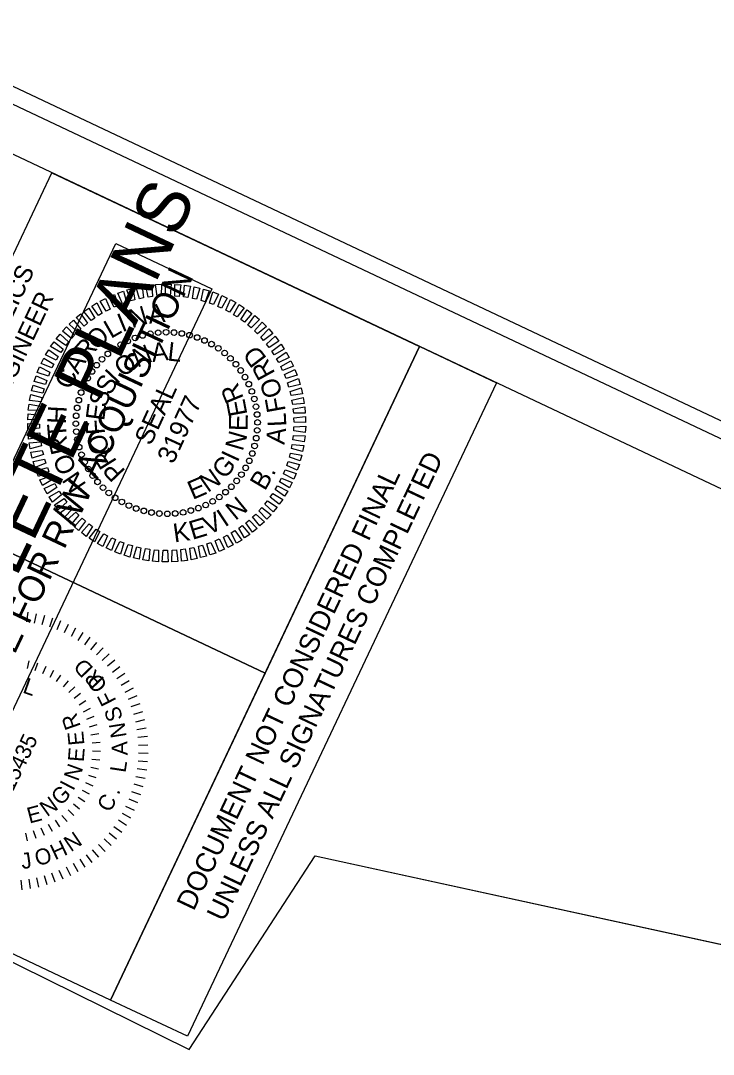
# Model space of a CAD drawing. Extents: x 555566 to 557881, y 503985 to 506091.
# Drawn here: x 556927.2 to 557118.8, y 505805.2 to 506091.2 of the extents above; entities that cross this region are included whole.
import ezdxf

# ---------------------------------------------------------------- set-up
doc = ezdxf.new("R2010")
doc.units = 0
for name, color, linetype in [('Matchline', 7, 'Continuous'), ('Old_Level_21', 7, 'Continuous'), ('Sheet Border Standard 30in CELL', 7, 'Continuous'), ('Sheet Clip Boundary CELL', 7, 'Continuous'), ('Sheet Plot Border Inside CELL', 7, 'Continuous'), ('Sheet Plot Border Outside CELL', 7, 'Continuous'), ('Sheet Sticker Exception Certification CELL', 7, 'Continuous'), ('Sheet Sticker Incomplete CELL', 7, 'Continuous')]:
    doc.layers.add(name, color=color, linetype=linetype)

msp = doc.modelspace()

# ---------------------------------------------------------------- linework, layer by layer
at = {"layer": 'Matchline'}
msp.add_line((557008.7, 505860.07), (557512.37, 505750.31), dxfattribs=at)
at = {"layer": 'Old_Level_21'}
for p, q in [((556929.21, 505927.52), (556928.84, 505924.91)), ((556931.52, 505927.12), (556930.99, 505924.54)), ((556933.79, 505926.59), (556933.11, 505924.04)), ((556936.03, 505925.91), (556935.19, 505923.41)), ((556938.22, 505925.11), (556937.23, 505922.66)), ((556940.36, 505924.17), (556939.23, 505921.79)), ((556942.44, 505923.1), (556941.17, 505920.8)), ((556944.45, 505921.92), (556943.05, 505919.69)), ((556946.39, 505920.61), (556944.85, 505918.47)), ((556948.24, 505919.19), (556946.58, 505917.14)), ((556950.01, 505917.66), (556948.22, 505915.71)), ((556929.48, 505914.07), (556928.99, 505911.93)), ((556951.68, 505916.02), (556949.77, 505914.19)), ((556953.24, 505914.29), (556951.24, 505912.58)), ((556931.85, 505913.4), (556931.16, 505911.32)), ((556934.15, 505912.51), (556933.26, 505910.51)), ((556936.35, 505911.4), (556935.27, 505909.49)), ((556954.7, 505912.46), (556952.6, 505910.88)), ((556937.1, 505908.33), (556938.36, 505910.13)), ((556940.38, 505908.58), (556938.95, 505906.91)), ((556956.05, 505910.55), (556953.85, 505909.1)), ((556957.28, 505908.57), (556955, 505907.25)), ((556942.17, 505906.88), (556940.58, 505905.36)), ((556958.38, 505906.51), (556956.03, 505905.33)), ((556943.78, 505905.03), (556942.06, 505903.67)), ((556945.22, 505903.03), (556943.37, 505901.83)), ((556959.37, 505904.39), (556956.94, 505903.35)), ((556960.22, 505902.21), (556957.73, 505901.33)), ((556946.45, 505900.89), (556944.5, 505899.88)), ((556960.94, 505899.99), (556958.4, 505899.25)), ((556947.47, 505898.65), (556945.43, 505897.83)), ((556961.52, 505897.72), (556958.95, 505897.14)), ((556948.27, 505896.32), (556946.16, 505895.71)), ((556948.84, 505893.92), (556946.68, 505893.52)), ((556961.96, 505895.43), (556959.36, 505895.01)), ((556949.18, 505891.48), (556946.99, 505891.29)), ((556962.27, 505893.12), (556959.65, 505892.85)), ((556962.43, 505890.78), (556959.8, 505890.68)), ((556949.27, 505889.02), (556947.08, 505889.04)), ((556962.45, 505888.45), (556959.82, 505888.5)), ((556949.14, 505886.56), (556946.95, 505886.79)), ((556962.34, 505886.11), (556959.71, 505886.32)), ((556948.15, 505881.74), (556946.05, 505882.38)), ((556948.76, 505884.12), (556946.61, 505884.56)), ((556962.08, 505883.79), (556959.47, 505884.16)), ((556947.32, 505879.42), (556945.29, 505880.27)), ((556961.15, 505879.21), (556958.6, 505879.9)), ((556961.68, 505881.49), (556959.1, 505882.02)), ((556946.26, 505877.19), (556944.32, 505878.23)), ((556960.47, 505876.98), (556957.98, 505877.81)), ((556941.82, 505874.48), (556943.52, 505873.08)), ((556945, 505875.08), (556943.17, 505876.3)), ((556958.73, 505872.64), (556956.35, 505873.77)), ((556959.67, 505874.78), (556957.22, 505875.77)), ((556940.07, 505869.61), (556938.66, 505871.3)), ((556941.89, 505871.27), (556940.32, 505872.82)), ((556957.67, 505870.56), (556955.36, 505871.83)), ((556935.99, 505866.84), (556934.94, 505868.77)), ((556938.1, 505868.12), (556936.86, 505869.94)), ((556955.17, 505866.61), (556953.03, 505868.15)), ((556956.48, 505868.55), (556954.25, 505869.96)), ((556929.09, 505864.28), (556928.63, 505866.43)), ((556931.47, 505864.91), (556930.81, 505867)), ((556933.78, 505865.76), (556932.92, 505867.79)), ((556953.75, 505864.76), (556951.71, 505866.42)), ((556950.58, 505861.33), (556948.76, 505863.23)), ((556952.22, 505862.99), (556950.28, 505864.78)), ((556947.03, 505858.3), (556945.44, 505860.41)), ((556948.85, 505859.76), (556947.14, 505861.77)), ((556941.07, 505854.62), (556939.89, 505856.97)), ((556943.13, 505855.72), (556941.81, 505858)), ((556945.11, 505856.95), (556943.66, 505859.15)), ((556929.99, 505851.04), (556929.57, 505853.64)), ((556932.28, 505851.48), (556931.71, 505854.06)), ((556934.55, 505852.07), (556933.81, 505854.6)), ((556936.77, 505852.79), (556935.89, 505855.27)), ((556938.95, 505853.63), (556937.92, 505856.06)), ((556927.68, 505850.73), (556927.41, 505853.36))]:
    msp.add_line(p, q, dxfattribs=at)
for points in [[(556957.7, 506013.68), (556956.61, 506016.72), (556958.23, 506017.14), (556958.84, 506014)], [(556960.08, 506014.29), (556959.2, 506017.4), (556960.85, 506017.7), (556961.24, 506014.53)], [(556962.5, 506014.73), (556961.84, 506017.9), (556963.51, 506018.08), (556963.67, 506014.89)], [(556964.94, 506015), (556964.51, 506018.21), (556966.18, 506018.28), (556966.12, 506015.08)], [(556967.4, 506015.1), (556967.19, 506018.33), (556968.86, 506018.28), (556968.58, 506015.1)], [(556969.86, 506015.03), (556969.87, 506018.27), (556971.54, 506018.1), (556971.04, 506014.95)], [(556972.3, 506014.79), (556972.54, 506018.02), (556974.19, 506017.74), (556973.47, 506014.62)], [(556974.73, 506014.38), (556975.19, 506017.58), (556976.82, 506017.19), (556975.88, 506014.13)], [(556977.12, 506013.8), (556977.8, 506016.96), (556979.4, 506016.45), (556978.25, 506013.47)], [(556950.89, 506010.88), (556949.19, 506013.63), (556950.69, 506014.37), (556951.94, 506011.43)], [(556953.09, 506011.97), (556951.59, 506014.83), (556953.14, 506015.47), (556954.18, 506012.45)], [(556955.37, 506012.9), (556954.07, 506015.86), (556955.65, 506016.39), (556956.48, 506013.3)], [(556979.46, 506013.06), (556980.36, 506016.16), (556981.92, 506015.54), (556980.57, 506012.65)], [(556981.74, 506012.15), (556982.86, 506015.18), (556984.37, 506014.46), (556982.82, 506011.66)], [(556983.96, 506011.08), (556985.29, 506014.03), (556986.74, 506013.21), (556985, 506010.53)], [(556946.74, 506008.25), (556944.67, 506010.73), (556946.06, 506011.68), (556947.7, 506008.94)], [(556948.77, 506009.64), (556946.88, 506012.26), (556948.33, 506013.11), (556949.78, 506010.26)], [(556986.1, 506009.87), (556987.63, 506012.72), (556989.02, 506011.79), (556987.1, 506009.24)], [(556988.14, 506008.51), (556989.87, 506011.24), (556991.19, 506010.22), (556989.1, 506007.81)], [(556943, 506005.07), (556940.6, 506007.24), (556941.84, 506008.37), (556943.85, 506005.88)], [(556944.81, 506006.72), (556942.58, 506009.06), (556943.89, 506010.1), (556945.72, 506007.48)], [(556990.09, 506007.01), (556992, 506009.61), (556993.25, 506008.5), (556990.99, 506006.24)], [(556941.3, 506003.29), (556938.76, 506005.29), (556939.92, 506006.5), (556942.1, 506004.16)], [(556991.93, 506005.37), (556994.01, 506007.84), (556995.19, 506006.64), (556992.77, 506004.55)], [(556993.64, 506003.62), (556995.9, 506005.93), (556996.99, 506004.66), (556994.43, 506002.73)], [(556938.3, 505999.4), (556935.51, 506001.03), (556936.48, 506002.39), (556938.97, 506000.37)], [(556939.73, 506001.39), (556937.06, 506003.21), (556938.13, 506004.5), (556940.46, 506002.32)], [(556995.24, 506001.74), (556997.65, 506003.9), (556998.64, 506002.55), (556995.96, 506000.81)], [(556937.01, 505997.3), (556934.11, 505998.73), (556934.99, 506000.16), (556937.61, 505998.33)], [(556996.69, 505999.76), (556999.25, 506001.74), (557000.15, 506000.33), (556997.35, 505998.78)], [(556998.01, 505997.69), (557000.7, 505999.48), (557001.49, 505998.01), (556998.6, 505996.66)], [(556935.87, 505995.13), (556932.88, 505996.35), (556933.65, 505997.83), (556936.39, 505996.19)], [(556999.18, 505995.52), (557001.98, 505997.13), (557002.68, 505995.6), (556999.69, 505994.46)], [(556934.88, 505992.87), (556931.81, 505993.89), (556932.48, 505995.42), (556935.33, 505993.97)], [(557000.19, 505993.28), (557003.1, 505994.69), (557003.69, 505993.12), (557000.63, 505992.18)], [(556934.06, 505990.56), (556930.92, 505991.35), (556931.49, 505992.93), (556934.43, 505991.68)], [(557001.05, 505990.98), (557004.05, 505992.18), (557004.52, 505990.57), (557001.41, 505989.85)], [(556933.4, 505988.19), (556930.21, 505988.77), (556930.66, 505990.38), (556933.69, 505989.34)], [(557001.74, 505988.62), (557004.82, 505989.61), (557005.18, 505987.97), (557002.02, 505987.47)], [(556932.57, 505983.35), (556929.34, 505983.47), (556929.56, 505985.13), (556932.7, 505984.52)], [(556932.9, 505985.78), (556929.68, 505986.14), (556930.02, 505987.78), (556933.11, 505986.95)], [(557002.26, 505986.22), (557005.41, 505986.99), (557005.65, 505985.33), (557002.47, 505985.05)], [(556932.42, 505980.89), (556929.18, 505980.8), (556929.29, 505982.47), (556932.46, 505982.08)], [(557002.62, 505983.79), (557005.81, 505984.33), (557005.94, 505982.66), (557002.74, 505982.61)], [(556932.43, 505978.44), (556929.21, 505978.11), (556929.2, 505979.79), (556932.4, 505979.62)], [(557002.81, 505981.34), (557006.03, 505981.66), (557006.04, 505979.99), (557002.85, 505980.15)], [(556932.62, 505975.99), (556929.43, 505975.44), (556929.3, 505977.11), (556932.5, 505977.16)], [(557002.82, 505978.88), (557006.06, 505978.98), (557005.95, 505977.31), (557002.78, 505977.69)], [(556932.98, 505973.55), (556929.84, 505972.78), (556929.59, 505974.44), (556932.78, 505974.72)], [(557002.34, 505973.99), (557005.56, 505973.64), (557005.22, 505972), (557002.13, 505972.82)], [(557002.67, 505976.42), (557005.9, 505976.3), (557005.68, 505974.64), (557002.54, 505975.25)], [(556933.5, 505971.15), (556930.42, 505970.17), (556930.06, 505971.8), (556933.22, 505972.3)], [(557001.85, 505971.58), (557005.03, 505971.01), (557004.58, 505969.39), (557001.55, 505970.43)], [(556934.19, 505968.79), (556931.19, 505967.59), (556930.72, 505969.2), (556933.83, 505969.92)], [(557001.18, 505969.21), (557004.32, 505968.42), (557003.75, 505966.84), (557000.81, 505968.09)], [(556935.05, 505966.49), (556932.14, 505965.08), (556931.55, 505966.65), (556934.61, 505967.59)], [(556936.06, 505964.25), (556933.26, 505962.64), (556932.57, 505964.17), (556935.55, 505965.31)], [(557000.36, 505966.9), (557003.43, 505965.89), (557002.76, 505964.35), (556999.91, 505965.8)], [(556937.23, 505962.09), (556934.54, 505960.29), (556933.75, 505961.76), (556936.64, 505963.11)], [(556998.23, 505962.47), (557001.13, 505961.04), (557000.25, 505959.61), (556997.63, 505961.45)], [(556999.37, 505964.65), (557002.36, 505963.42), (557001.59, 505961.94), (556998.85, 505963.58)], [(556938.55, 505960.01), (556935.99, 505958.03), (556935.09, 505959.44), (556937.89, 505960.99)], [(556996.94, 505960.38), (556999.73, 505958.75), (556998.76, 505957.39), (556996.27, 505959.4)], [(556940, 505958.03), (556937.59, 505955.88), (556936.6, 505957.22), (556939.28, 505958.97)], [(556941.6, 505956.16), (556939.34, 505953.84), (556938.26, 505955.12), (556940.81, 505957.04)], [(556995.51, 505958.38), (556998.18, 505956.56), (556997.11, 505955.27), (556994.78, 505957.45)], [(556943.31, 505954.4), (556941.23, 505951.93), (556940.05, 505953.13), (556942.47, 505955.22)], [(556992.24, 505954.71), (556994.64, 505952.53), (556993.4, 505951.4), (556991.39, 505953.89)], [(556993.94, 505956.48), (556996.48, 505954.48), (556995.32, 505953.27), (556993.14, 505955.61)], [(556945.15, 505952.77), (556943.24, 505950.16), (556941.99, 505951.27), (556944.25, 505953.53)], [(556947.1, 505951.26), (556945.37, 505948.53), (556944.05, 505949.55), (556946.14, 505951.96)], [(556988.5, 505951.52), (556990.57, 505949.04), (556989.18, 505948.09), (556987.54, 505950.83)], [(556990.43, 505953.05), (556992.66, 505950.71), (556991.35, 505949.67), (556989.52, 505952.29)], [(556949.15, 505949.9), (556947.61, 505947.05), (556946.22, 505947.98), (556948.14, 505950.53)], [(556951.28, 505948.69), (556949.95, 505945.74), (556948.5, 505946.57), (556950.24, 505949.25)], [(556953.5, 505947.62), (556952.38, 505944.59), (556950.87, 505945.31), (556952.42, 505948.11)], [(556984.35, 505948.89), (556986.05, 505946.14), (556984.55, 505945.4), (556983.3, 505948.34)], [(556986.47, 505950.14), (556988.36, 505947.51), (556986.91, 505946.67), (556985.46, 505949.51)], [(556955.78, 505946.72), (556954.88, 505943.61), (556953.32, 505944.23), (556954.67, 505947.13)], [(556958.13, 505945.97), (556957.44, 505942.81), (556955.84, 505943.32), (556956.99, 505946.3)], [(556960.51, 505945.39), (556960.05, 505942.19), (556958.42, 505942.59), (556959.36, 505945.64)], [(556962.94, 505944.98), (556962.7, 505941.76), (556961.05, 505942.04), (556961.77, 505945.15)], [(556975.16, 505945.48), (556976.04, 505942.37), (556974.39, 505942.07), (556974, 505945.24)], [(556977.54, 505946.09), (556978.63, 505943.05), (556977.01, 505942.63), (556976.4, 505945.77)], [(556979.87, 505946.87), (556981.18, 505943.91), (556979.59, 505943.38), (556978.76, 505946.47)], [(556982.15, 505947.8), (556983.65, 505944.94), (556982.1, 505944.3), (556981.06, 505947.33)], [(556965.38, 505944.74), (556965.37, 505941.51), (556963.7, 505941.67), (556964.2, 505944.83)], [(556967.84, 505944.67), (556968.05, 505941.44), (556966.38, 505941.49), (556966.66, 505944.67)], [(556970.3, 505944.77), (556970.73, 505941.57), (556969.06, 505941.5), (556969.12, 505944.69)], [(556972.74, 505945.04), (556973.4, 505941.88), (556971.73, 505941.69), (556971.57, 505944.88)]]:
    msp.add_lwpolyline(points, close=True, dxfattribs=at)
for centre in [(556963.09, 506004.6), (556965.26, 506004.9), (556967.45, 506005.01), (556969.64, 506004.93), (556971.81, 506004.66), (556954.91, 506001.56), (556956.84, 506002.58), (556958.86, 506003.44), (556960.95, 506004.11), (556973.95, 506004.2), (556976.05, 506003.56), (556978.08, 506002.73), (556980.03, 506001.73), (556951.34, 505999.02), (556953.07, 506000.37), (556981.89, 506000.57), (556983.64, 505999.25), (556948.26, 505995.9), (556949.73, 505997.53), (556985.26, 505997.78), (556986.75, 505996.17), (556946.94, 505994.15), (556988.1, 505994.44), (556944.78, 505990.35), (556945.77, 505992.3), (556989.29, 505992.6), (556990.32, 505990.66), (556943.95, 505988.32), (556991.17, 505988.64), (556943.31, 505986.22), (556991.84, 505986.56), (556992.33, 505984.42), (556942.58, 505981.9), (556942.85, 505984.08), (556992.63, 505982.25), (556942.49, 505979.71), (556992.75, 505980.06), (556942.61, 505977.52), (556992.66, 505977.87), (556942.91, 505975.35), (556943.4, 505973.21), (556991.93, 505973.55), (556992.39, 505975.7), (556944.07, 505971.13), (556991.29, 505971.46), (556944.92, 505969.11), (556989.47, 505967.47), (556990.47, 505969.43), (556945.95, 505967.17), (556947.14, 505965.33), (556988.3, 505965.62), (556948.49, 505963.6), (556949.98, 505962), (556985.51, 505962.24), (556986.98, 505963.87), (556951.6, 505960.53), (556953.35, 505959.2), (556982.17, 505959.4), (556983.9, 505960.75), (556955.21, 505958.04), (556957.16, 505957.04), (556959.19, 505956.22), (556976.38, 505956.34), (556978.4, 505957.19), (556980.33, 505958.21), (556961.29, 505955.57), (556963.43, 505955.11), (556965.6, 505954.84), (556967.79, 505954.76), (556969.98, 505954.87), (556972.16, 505955.17), (556974.29, 505955.66)]:
    msp.add_circle(centre, 0.777, dxfattribs=at)
at = {"layer": 'Sheet Border Standard 30in CELL'}
msp.add_line((556893.15, 505958.73), (556994.82, 505910.68), dxfattribs=at)
for points in [[(556901.93, 506065.19), (556260.95, 504709.04), (557210.25, 504260.35), (557851.24, 505616.5)], [(556893.15, 505958.73), (556935.88, 506049.14), (557037.59, 506001.07), (556994.86, 505910.66)], [(556850.4, 505868.28), (556893.15, 505958.73), (556994.86, 505910.66), (556952.11, 505820.2)]]:
    msp.add_lwpolyline(points, close=True, dxfattribs=at)
at = {"layer": 'Sheet Clip Boundary CELL'}
msp.add_lwpolyline([(557047.43, 504351.91), (557011.84, 504393.69), (556904.12, 504418.34), (556404.92, 505013.64), (556816.45, 505884.32), (556973.87, 505806.54), (557008.7, 505860.07), (557008.7, 505860.07), (557512.37, 505750.31), (557851.24, 505616.5), (557197.58, 504288.36)], close=True, dxfattribs=at)
at = {"layer": 'Sheet Plot Border Inside CELL'}
msp.add_lwpolyline([(556904.97, 506077.58), (556192.83, 504570.9), (557146.75, 504120.03), (557858.88, 505626.71)], close=True, dxfattribs=at)
at = {"layer": 'Sheet Plot Border Outside CELL'}
msp.add_lwpolyline([(556886.6, 506091.24), (556166.98, 504568.74), (557161.49, 504098.68), (557881.1, 505621.18)], close=True, dxfattribs=at)
at = {"layer": 'Sheet Sticker Exception Certification CELL'}
for p, q in [((556952.11, 505820.2), (557037.59, 506001.06)), ((557037.6, 506001.05), (557058.85, 505991.01)), ((557058.83, 505991.01), (556973.35, 505810.16)), ((556973.35, 505810.16), (556952.11, 505820.2))]:
    msp.add_line(p, q, dxfattribs=at)
at = {"layer": 'Sheet Sticker Incomplete CELL'}
msp.add_lwpolyline([(556901.55, 505850.92), (556874.99, 505863.48), (556953.52, 506029.6), (556980.07, 506017.05)], close=True, dxfattribs=at)

# ---------------------------------------------------------------- texts
at = {"layer": 'Old_Level_21'}
for s, height, rotation, p in [('N', 5.18, 16.469, (556957.99, 506006.08)), ('A', 5.18, 6.2586, (556962.78, 506007.37)), ('L', 5.18, 29.8741, (556952.18, 506003.13)), ('I', 5.18, 22.4089, (556955.33, 506004.94)), ('O', 5.18, 40.5993, (556948.12, 505999.85)), ('R', 5.18, 48.8079, (556945.47, 505996.86)), ('L', 5.18, 353.7542, (556967.69, 505997.21)), ('N', 5.18, 22.1402, (556959.45, 505995.16)), ('A', 5.18, 7.0901, (556963.69, 505996.76)), ('D', 5.18, 127.0991, (556995.47, 505997.81)), ('A', 5.18, 57.8554, (556943.08, 505993.17)), ('O', 5.18, 37.949, (556955.6, 505992.35)), ('R', 5.18, 118.8904, (556997.75, 505993.65)), ('C', 5.18, 67.3604, (556941.22, 505988.93)), ('I', 5.18, 46.7044, (556953.84, 505990.38)), ('S', 5.18, 58.6634, (556951.96, 505987.3)), ('R', 5.18, 112.4416, (556989.02, 505986.76)), ('O', 5.18, 108.1653, (556999.78, 505987.8)), ('S', 5.18, 70.6223, (556950.77, 505983.89)), ('SEAL', 5.181, 65.3986, (556963.22, 505973.38)), ('E', 5.18, 82.3846, (556950.31, 505980.37)), ('31977', 5.181, 65.3986, (556969.45, 505968.33)), ('E', 5.18, 100.6793, (556989.97, 505982.26)), ('F', 5.18, 100.2426, (557000.57, 505983.29)), ('H', 5.18, 86.9996, (556939.72, 505979.53)), ('L', 5.18, 92.7775, (557000.73, 505978.98)), ('T', 5.18, 94.7889, (556940.02, 505975.75)), ('F', 5.18, 94.0625, (556950.57, 505976.86)), ('E', 5.18, 88.9171, (556989.99, 505977.65)), ('N', 5.18, 73.867, (556988.64, 505971.92)), ('A', 5.18, 83.73, (557000.17, 505973.79)), ('R', 5.18, 102.9975, (556940.9, 505971.86)), ('O', 5.18, 109.8713, (556952.04, 505972.33)), ('O', 5.18, 113.7227, (556942.86, 505967.02)), ('R', 5.18, 121.9707, (556953.97, 505969.23)), ('I', 5.18, 65.1116, (556987.18, 505968.81)), ('G', 5.18, 50.0615, (556983.64, 505964.11)), ('N', 5.18, 123.9331, (556945.53, 505962.84)), ('P', 5.18, 133.733, (556956.43, 505966.67)), ('N', 5.18, 35.0115, (556978.99, 505960.49)), ('B', 5.18, 59.4186, (556994.78, 505960.92)), ('.', 5.18, 67.7607, (556997.24, 505965.06)), ('E', 5.18, 23.2492, (556974.8, 505958.58)), ('N', 5.18, 39.3218, (556986.61, 505952.75)), ('E', 5.18, 16.7167, (556974.72, 505947.53)), ('V', 5.18, 24.6966, (556979.14, 505948.83)), ('I', 5.18, 33.3819, (556983.7, 505950.93)), ('K', 5.18, 8.0124, (556969.74, 505946.83)), (' RD', 4.391, 134.2947, (556951.69, 505907.88)), ('L', 4.39, 340.4929, (556927.54, 505905.35)), ('O ', 4.391, 125.6219, (556951.43, 505907.29)), ('F', 4.39, 116.8293, (556953.79, 505903.01)), ('R', 4.39, 109.1871, (556943.91, 505895.95)), ('S', 4.39, 107.9467, (556955.59, 505898.11)), ('N', 4.39, 99.0641, (556956.58, 505893.09)), ('15435', 4.391, 64.6223, (556925.08, 505877.72)), ('E', 4.39, 95.4161, (556944.88, 505890.86)), ('A', 4.39, 90.2414, (556956.79, 505887.94)), ('E', 4.39, 85.4302, (556944.65, 505885.99)), ('N', 4.39, 70.0381, (556943.15, 505880.54)), ('L', 4.39, 81.2389, (556956.21, 505882.96)), ('G', 4.39, 44.3137, (556938.23, 505873.79)), ('I', 4.39, 62.4085, (556941.74, 505877.91)), ('N', 4.39, 35.5474, (556934.52, 505870.79)), ('C', 4.39, 60.7122, (556951.91, 505871.9)), ('.', 4.39, 68.4546, (556954.35, 505876.78)), ('E', 4.39, 14.6923, (556929.64, 505869.02)), ('N', 4.39, 33.9444, (556941.09, 505861.08)), ('O', 4.39, 16.6291, (556931.86, 505857.19)), ('H', 4.39, 25.2718, (556936.74, 505858.84)), ('J', 4.39, 8.5573, (556927.63, 505856.42))]:
    msp.add_text(s, height=height, rotation=rotation, dxfattribs=at).set_placement(p)
at = {"layer": 'Sheet Border Standard 30in CELL'}
for s, p in [('HYDRAULICS', (556912.76, 505983.14)), ('ENGINEER', (556921.57, 505983.18))]:
    msp.add_text(s, height=5, rotation=64.7021, dxfattribs=at).set_placement(p)
at = {"layer": 'Sheet Sticker Exception Certification CELL'}
for s, p in [('UNLESS ALL SIGNATURES COMPLETED', (556983.43, 505841.66)), ('DOCUMENT NOT CONSIDERED FINAL', (556975.09, 505844.63))]:
    msp.add_text(s, height=5.5, rotation=64.7021, dxfattribs=at).set_placement(p)
at = {"layer": 'Sheet Sticker Incomplete CELL'}
for s, height, p in [('INCOMPLETE PLANS', 14.4, (556893.1, 505867.31)), ('DO NOT USE FOR R/W ACQUISITION', 7.2, (556902.69, 505867.27))]:
    msp.add_text(s, height=height, rotation=64.7021, dxfattribs=at).set_placement(p)

doc.saveas('drawing.dxf')
